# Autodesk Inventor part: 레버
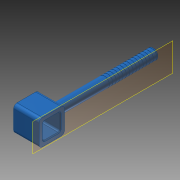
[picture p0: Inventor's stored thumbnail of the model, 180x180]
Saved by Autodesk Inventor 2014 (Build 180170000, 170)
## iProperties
Created: 2015-12
Part Number: 레버
Material: 스테인리스강
Document SubType Name: Modeling
Designer: mduedu
Density: 8.08 g/cm^3
Mass: 30.6794 g
Surface Area: 23.0487 cm^2
Volume: 3.79696 cm^3
Appearance: 청록색
Author: mduedu
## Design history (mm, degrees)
sketch "스케치1"
  geometry: C1 r 3 at (0, 0); 1 further point
  constraints: 1 centre point, 1 coincident
  dimensions: "d0" = 6 diameter of C1
extrude "돌출1" new body sketch "스케치1" distance "d1" = 60; taper "d2" = 0 deg
sketch "스케치5"
  geometry: L1 (-7.5, -7.5)-(7.5, -7.5); L2 (7.5, -7.5)-(7.5, 7.5); L3 (7.5, 7.5)-(-7.5, 7.5); L4 (-7.5, 7.5)-(-7.5, -7.5); L5 (-7.5, -7.5)-(7.5, 7.5); L6 (7.5, -7.5)-(-7.5, 7.5); C1 r 3 at (0, 0) reference
  constraints: 12 end point, 2 midpoint, 2 parallel, 2 perpendicular, 1 horizontal
  dimensions: "d24" = 15 distance of L2.end L3.end
extrude "돌출2" join sketch "스케치5" distance "d26" = 15; taper "d27" = 0 deg
chamfer "모따기1" distance "d7" = 0.5; stored, may be unused: second distance "d8" = 2, angle "d9" = 45 deg
fillet "모깎기2" dims "d11" = 1
sketch "스케치4"
  geometry: L1 (-60, -2.5)-(-60, 2.5) reference; L2 (-60, 0)-(0, 0); L3 (-1, 3)-(-59.5, 3) reference; L4 (-59, 3)-(-58.9, 3); L5 (-58.9, 3)-(-58.9, 2.9); L6 (-58.9, 2.9)-(-59, 2.9); L7 (-59, 2.9)-(-59, 3)
  constraints: 10 end point, 2 parallel, 2 perpendicular, 1 horizontal, 1 midpoint, 1 point on line
  dimensions: "d17" = 1 distance between parallel lines of L7 L1; "d18" = 0.1 distance of L5.end L6.end; "d19" = 0.1 distance of L4.end L5.end
revolve "회전3" sketch "스케치4" stored, may be unused: angle "d20" = 90 deg
sketch "스케치6"
  geometry: L1 (0, 0)-(15, 0) reference; L2 (15, 15)-(15, 0) reference; L3 (0, 15)-(15, 15) reference; L4 (7.5, 15)-(7.5, 0); L5 (0, 7.5)-(15, 7.5); L6 (2.5, 2.5)-(12.5, 2.5); L7 (12.5, 2.5)-(12.5, 12.5); L8 (12.5, 12.5)-(2.5, 12.5); L9 (2.5, 12.5)-(2.5, 2.5); L10 (2.5, 2.5)-(12.5, 12.5); L11 (12.5, 2.5)-(2.5, 12.5); 1 further point
  constraints: 16 end point, 6 midpoint, 2 parallel, 2 perpendicular, 1 horizontal
  dimensions: "d29" = 10 distance of L7.end L8.end; "d31" = 2.5 distance between parallel lines of L8 L3 (derived)
extrude "돌출3" cut sketch "스케치6" stored distance "d32" = 15; taper "d33" = 0 deg
fillet "모깎기3" dims "d34" = 2, "d35" = 1
chamfer "모따기2" distance "d36" = 0.5; stored, may be unused: second distance "d37" = 2, angle "d38" = 45 deg
node "작업 평면1"
node "솔리드1"
pattern_linear "직사각형 패턴1" dims "d23" = 2
